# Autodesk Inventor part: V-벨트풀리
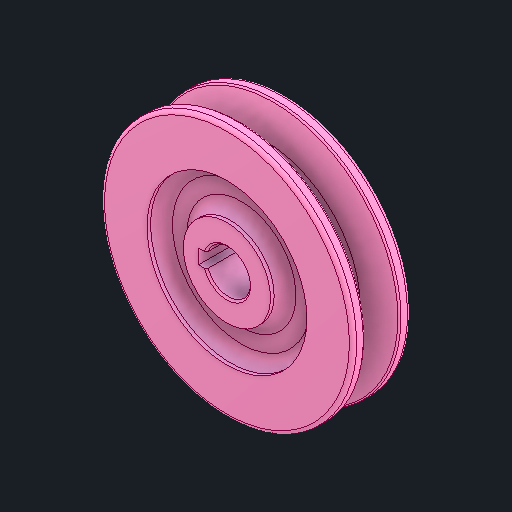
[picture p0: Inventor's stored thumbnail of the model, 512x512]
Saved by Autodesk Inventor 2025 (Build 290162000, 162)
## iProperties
Created: 2025-08
Part Number: V-벨트풀리
Material: 강철, 연강
Document SubType Name: Modeling
Designer: infra005
Density: 7.86 g/cm^3
Appearance: 기본값
Author: jhkim
Sending System: Autodesk Inventor 2026
Preprocessor: ST-DEVELOPER v20.1
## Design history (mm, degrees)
feature "Solid1"
node "솔리드1"
